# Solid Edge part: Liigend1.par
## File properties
Author: Türk
Template: Iso Part.par
Last saved by: Türk
Revision: 12
Application: Solid Edge
Accuracy: 0,990
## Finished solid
Body 1: solid body, 19 faces, 39 edges, 20 vertices.
  Faces by surface: plane 9, cylinder 8, cone 1, torus 1
  Edges by curve: line 22, circle 17
Body 2: sheet body, 3 faces, 28 edges, 28 vertices.
  Faces by surface: plane 3
  Edges by curve: line 24, circle 4
Bounding box of the edges (mm; curved faces can reach further): 50.000 x 107.500 x 70.000, from (-25, -55, -35) to (25, 52.5, 35).
Cylindrical faces by radius (mm): R5 x2, R10 x2, R10.5 x2, R25 x2
Conical faces (half-angle, radius in mm at the cone's reference point): 45 deg R9 x1
Toroidal faces (ring radius, tube radius in mm): R10 r2.5 x1
Planar faces by outward normal: +x 1, +y 2, +z 2, -x 1, -y 1, -z 2
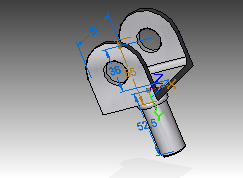
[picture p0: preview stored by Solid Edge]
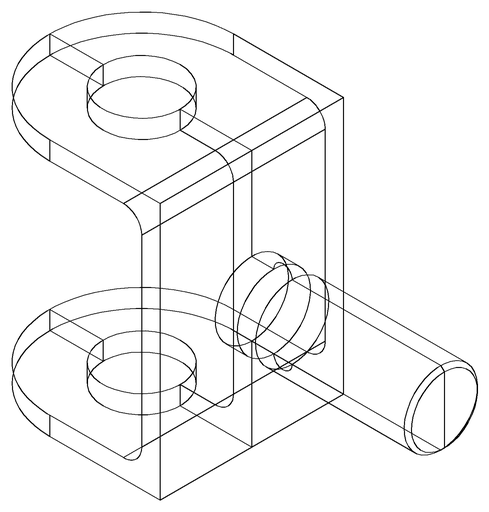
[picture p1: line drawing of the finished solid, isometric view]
